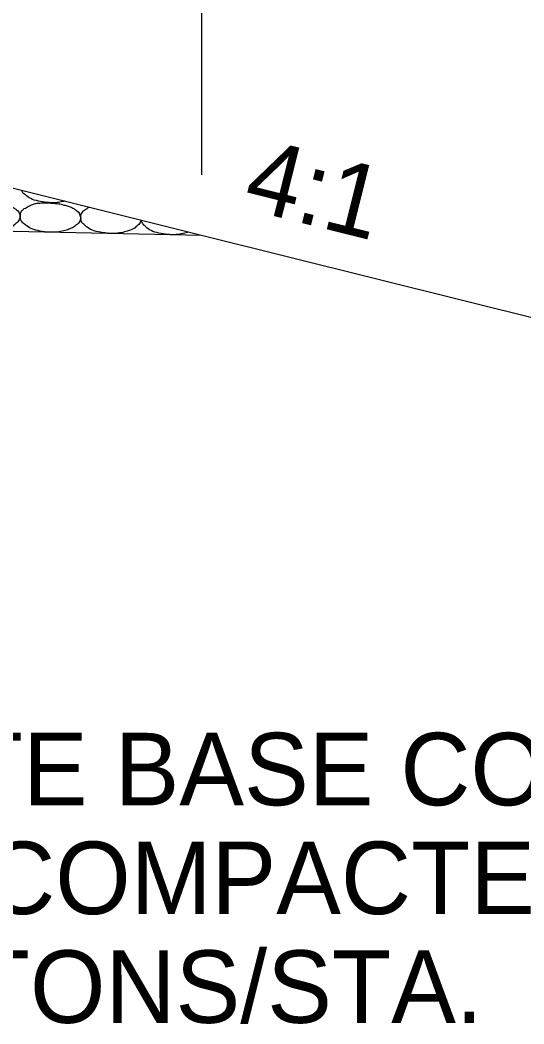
# Model space of a CAD drawing. Extents: x 2263886 to 2266026, y -3122850 to -3121850.
# Drawn here: x 2265530.71 to 2265534.88, y -3122293.5 to -3122285.19 of the extents above; entities that cross this region are included whole.
import ezdxf

# ---------------------------------------------------------------- set-up
doc = ezdxf.new("R2010")
doc.units = 0
doc.layers.add('R_Border Prem', color=7, linetype='Continuous')

msp = doc.modelspace()

# ---------------------------------------------------------------- linework, layer by layer
at = {"layer": 'R_Border Prem'}
for p, q in [((2265532.2124, -3122277.9935), (2265532.2124, -3122286.4733)), ((2265532.2124, -3122286.9733), (2265526.568, -3122285.5622)), ((2265532.2124, -3122286.9733), (2265513.5646, -3122286.6003)), ((2265538.568, -3122288.5622), (2265532.2124, -3122286.9733))]:
    msp.add_line(p, q, dxfattribs=at)
for points in [[(2265531.0805, -3122286.6903), (2265531.0785, -3122286.6907), (2265531.054, -3122286.696), (2265531.0069, -3122286.7051), (2265530.9358, -3122286.7025), (2265530.8623, -3122286.691), (2265530.7954, -3122286.6716), (2265530.7517, -3122286.6359), (2265530.7291, -3122286.6155), (2265530.7229, -3122286.6017), (2265530.7225, -3122286.6008)], [(2265530.6935, -3122286.7711), (2265530.6981, -3122286.7753), (2265530.7036, -3122286.7867), (2265530.708, -3122286.8043), (2265530.7156, -3122286.8201), (2265530.7076, -3122286.8377), (2265530.7002, -3122286.8536), (2265530.6856, -3122286.8708), (2265530.6669, -3122286.8814), (2265530.655, -3122286.8985), (2265530.6348, -3122286.902), (2265530.6087, -3122286.9169), (2265530.5618, -3122286.9282), (2265530.5012, -3122286.9396), (2265530.4301, -3122286.9371), (2265530.3567, -3122286.9256), (2265530.2898, -3122286.9062), (2265530.246, -3122286.8705), (2265530.2151, -3122286.843), (2265530.2122, -3122286.8139), (2265530.2122, -3122286.7888), (2265530.2185, -3122286.7678), (2265530.2311, -3122286.7536), (2265530.2446, -3122286.7416), (2265530.2642, -3122286.7335), (2265530.2811, -3122286.7202), (2265530.3056, -3122286.7118), (2265530.3362, -3122286.6976), (2265530.3858, -3122286.6955), (2265530.4386, -3122286.6931), (2265530.4914, -3122286.6989), (2265530.5321, -3122286.7003), (2265530.5671, -3122286.711), (2265530.601, -3122286.7171), (2265530.6332, -3122286.7294), (2265530.6622, -3122286.7459), (2265530.6814, -3122286.762), (2265530.6946, -3122286.7713), (2265530.6979, -3122286.7757)], [(2265531.1943, -3122286.7811), (2265531.1989, -3122286.7853), (2265531.2044, -3122286.7967), (2265531.2088, -3122286.8143), (2265531.2164, -3122286.8301), (2265531.2084, -3122286.8477), (2265531.201, -3122286.8636), (2265531.1864, -3122286.8808), (2265531.1677, -3122286.8915), (2265531.1557, -3122286.9085), (2265531.1355, -3122286.912), (2265531.1095, -3122286.9269), (2265531.0626, -3122286.9382), (2265531.002, -3122286.9496), (2265530.9309, -3122286.9471), (2265530.8575, -3122286.9356), (2265530.7905, -3122286.9162), (2265530.7468, -3122286.8805), (2265530.7159, -3122286.853), (2265530.713, -3122286.8239), (2265530.7129, -3122286.7988), (2265530.7193, -3122286.7778), (2265530.7319, -3122286.7636), (2265530.7453, -3122286.7516), (2265530.765, -3122286.7435), (2265530.7819, -3122286.7302), (2265530.8064, -3122286.7219), (2265530.837, -3122286.7077), (2265530.8866, -3122286.7055), (2265530.9393, -3122286.7031), (2265530.9922, -3122286.709), (2265531.0329, -3122286.7103), (2265531.0679, -3122286.721), (2265531.1018, -3122286.7271), (2265531.1339, -3122286.7394), (2265531.163, -3122286.756), (2265531.1822, -3122286.772), (2265531.1954, -3122286.7813), (2265531.1987, -3122286.7857)], [(2265531.7127, -3122286.8484), (2265531.7121, -3122286.8504), (2265531.7084, -3122286.8595), (2265531.7018, -3122286.8736), (2265531.6872, -3122286.8908), (2265531.6685, -3122286.9015), (2265531.6565, -3122286.9185), (2265531.6363, -3122286.922), (2265531.6103, -3122286.9369), (2265531.5634, -3122286.9482), (2265531.5028, -3122286.9597), (2265531.4317, -3122286.9571), (2265531.3582, -3122286.9456), (2265531.2913, -3122286.9262), (2265531.2476, -3122286.8905), (2265531.2167, -3122286.863), (2265531.2138, -3122286.8339), (2265531.2137, -3122286.8089), (2265531.2201, -3122286.7879), (2265531.2327, -3122286.7736), (2265531.2461, -3122286.7617), (2265531.2647, -3122286.7538), (2265531.2755, -3122286.7437), (2265531.282, -3122286.7407)], [(2265532.1071, -3122286.9469), (2265532.0953, -3122286.9508), (2265532.0609, -3122286.9588), (2265532.0036, -3122286.9697), (2265531.9325, -3122286.9671), (2265531.859, -3122286.9556), (2265531.7921, -3122286.9362), (2265531.7484, -3122286.9006), (2265531.7198, -3122286.875), (2265531.7162, -3122286.8555), (2265531.7155, -3122286.8491)]]:
    msp.add_open_spline(points, degree=3, dxfattribs=at)

# ---------------------------------------------------------------- texts
msp.add_text('4:1', height=0.6, rotation=345.96376, dxfattribs=at).set_placement((2265532.5398, -3122286.7459))
for s, p in [('AGGREGATE BASE COURSE', (2265526.1881, -3122291.6884)), ('(CLASS 7) VAR. COMPACTED DEPTH', (2265524.27, -3122292.5884)), ('90.00 TONS/STA.', (2265528.0731, -3122293.4884))]:
    msp.add_text(s, height=0.6, dxfattribs=at).set_placement(p)

doc.saveas('drawing.dxf')
